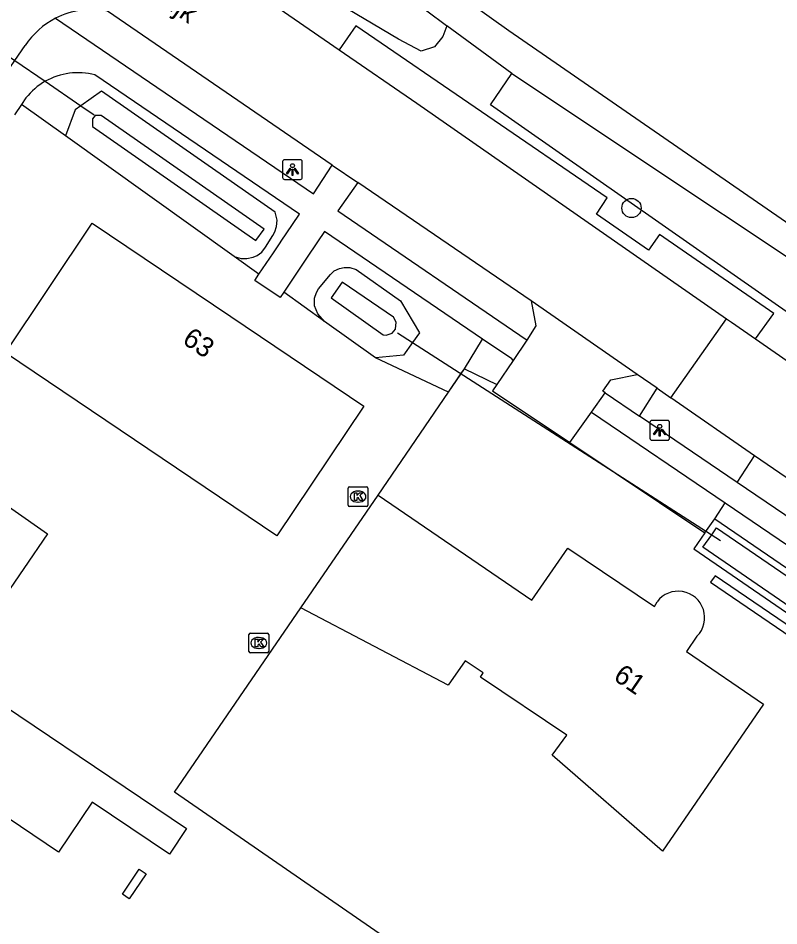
# Model space of a CAD drawing. Extents: x 163863 to 164644, y 379566 to 382155.
# Drawn here: x 164198.04 to 164236.59, y 381807.43 to 381853.41 of the extents above; entities that cross this region are included whole.
import ezdxf

# ---------------------------------------------------------------- set-up
doc = ezdxf.new("R2010")
doc.units = 0
for name, color, linetype in [('IMGEO_Boom', 7, 'Continuous'), ('IMGEO_Duiker', 7, 'Continuous'), ('IMGEO_Erf', 7, 'Continuous'), ('IMGEO_Grasland_overig', 7, 'Continuous'), ('IMGEO_Groenvoorziening', 7, 'Continuous'), ('IMGEO_Haag', 7, 'Continuous'), ('IMGEO_Kolk', 7, 'Continuous'), ('IMGEO_Lichtpunt', 7, 'Continuous'), ('IMGEO_Muur', 7, 'Continuous'), ('IMGEO_Openbare_ruimte_label', 7, 'Continuous'), ('IMGEO_Pand', 7, 'Continuous'), ('IMGEO_Pand_nummerreeks', 7, 'Continuous'), ('IMGEO_Parkeervlak_halfverhard', 7, 'Continuous'), ('IMGEO_Parkeervlak_open', 7, 'Continuous'), ('IMGEO_Rijbaan_lokaal_gesloten', 7, 'Continuous'), ('IMGEO_Rijbaan_lokaal_open', 7, 'Continuous'), ('IMGEO_Sloot', 7, 'Continuous'), ('IMGEO_Voetpad_open', 7, 'Continuous'), ('IMGEO_Waterloop', 7, 'Continuous')]:
    doc.layers.add(name, color=color, linetype=linetype)

msp = doc.modelspace()

# ---------------------------------------------------------------- linework, layer by layer
at = {"layer": 'IMGEO_Boom'}
msp.add_circle((164229.12, 381843.797), 0.489, dxfattribs=at)
at = {"layer": 'IMGEO_Duiker'}
for points in [[(164190.042, 381856.658), (164190.846, 381856.104), (164192.323, 381855.089), (164194.104, 381853.864), (164197.871, 381851.272), (164199.409, 381850.214), (164201.216, 381848.971), (164201.883, 381848.512)], [(164217.268, 381837.469), (164218.022, 381836.985), (164233.632, 381826.955)]]:
    msp.add_lwpolyline(points, dxfattribs=at)
at = {"layer": 'IMGEO_Erf'}
for points in [[(164208.977, 381841.341), (164200.437, 381847.454)], [(164216.141, 381836.213), (164213.566, 381838.056)], [(164216.274, 381829.253), (164219.843, 381834.466)], [(164232.842, 381827.338), (164232.273, 381826.526), (164254.142, 381811.525), (164254.893, 381811.01), (164255.882, 381812.656)], [(164234.237, 381791.715), (164235.601, 381793.483), (164235.285, 381793.932), (164235.043, 381794.138), (164205.955, 381814.209), (164212.364, 381823.54)]]:
    msp.add_lwpolyline(points, dxfattribs=at)
at = {"layer": 'IMGEO_Grasland_overig'}
for points in [[(164335.006, 381775.051), (164322.428, 381783.408), (164286.005, 381809.753), (164256.457, 381829.627), (164222.906, 381852.769), (164211.763, 381860.7), (164201.663, 381868.745), (164208.654, 381876.058), (164252.396, 381909.265)], [(164223.061, 381850.617), (164219.769, 381853.023)], [(164208.977, 381841.341), (164209.344, 381841.247), (164209.632, 381841.24), (164209.943, 381841.299), (164210.157, 381841.388), (164210.386, 381841.558), (164210.564, 381841.812), (164210.941, 381842.409), (164211.052, 381842.593), (164211.125, 381842.859), (164211.155, 381843.184), (164211.061, 381843.586), (164202.265, 381849.716), (164201.216, 381848.971), (164200.931, 381848.768), (164200.437, 381847.454)], [(164200.437, 381847.454), (164198.212, 381849.047)], [(164210.234, 381840.441), (164208.977, 381841.341)]]:
    msp.add_lwpolyline(points, dxfattribs=at)
at = {"layer": 'IMGEO_Groenvoorziening'}
for points in [[(164213.566, 381838.056), (164213.223, 381838.437), (164213.061, 381838.836), (164213.061, 381839.228), (164213.15, 381839.509), (164213.258, 381839.698), (164213.869, 381840.436), (164214.044, 381840.618), (164214.325, 381840.736), (164214.561, 381840.788), (164214.849, 381840.78), (164215.169, 381840.688), (164217.418, 381839.098), (164218.372, 381837.475), (164218.022, 381836.985), (164217.566, 381836.344), (164216.141, 381836.213)], [(164213.566, 381838.056), (164211.492, 381839.541)], [(164220.66, 381835.65), (164221.574, 381837.159)], [(164219.843, 381834.466), (164216.141, 381836.213)], [(164219.843, 381834.466), (164220.66, 381835.65)], [(164220.66, 381835.65), (164222.298, 381834.862)], [(164233.34, 381828.049), (164255.882, 381812.656)]]:
    msp.add_lwpolyline(points, dxfattribs=at)
at = {"layer": 'IMGEO_Haag'}
msp.add_lwpolyline([(164233.352, 381825.171), (164233.126, 381824.841), (164253.669, 381810.851), (164253.894, 381811.182), (164233.352, 381825.171)], dxfattribs=at)
at = {"layer": 'IMGEO_Kolk'}
for p, q in [((164214.759, 381828.751), (164214.759, 381829.603)), ((164214.834, 381829.677), (164215.686, 381829.677)), ((164215.247, 381829.457), (164215.272, 381829.457)), ((164215.76, 381829.603), (164215.76, 381828.751)), ((164215.686, 381828.677), (164214.834, 381828.677)), ((164215.27, 381828.897), (164215.245, 381828.897)), ((164209.734, 381821.337), (164209.734, 381822.189)), ((164209.809, 381822.263), (164210.661, 381822.263)), ((164210.735, 381822.189), (164210.735, 381821.337)), ((164210.222, 381822.043), (164210.247, 381822.043)), ((164210.661, 381821.263), (164209.809, 381821.263)), ((164210.245, 381821.483), (164210.22, 381821.483))]:
    msp.add_line(p, q, dxfattribs=at)
for points in [[(164214.759, 381828.751), (164214.759, 381829.603)], [(164214.834, 381829.677), (164215.686, 381829.677)], [(164215.76, 381829.603), (164215.76, 381828.751)], [(164215.08, 381829.377), (164215.203, 381829.377), (164215.203, 381829.226), (164215.333, 381829.377), (164215.497, 381829.377), (164215.351, 381829.226), (164215.504, 381828.977), (164215.352, 381828.977), (164215.267, 381829.141), (164215.203, 381829.074), (164215.203, 381828.977), (164215.08, 381828.977), (164215.08, 381829.377)], [(164215.686, 381828.677), (164214.834, 381828.677)], [(164209.734, 381821.337), (164209.734, 381822.189)], [(164209.809, 381822.263), (164210.661, 381822.263)], [(164210.735, 381822.189), (164210.735, 381821.337)], [(164210.055, 381821.963), (164210.178, 381821.963), (164210.178, 381821.812), (164210.308, 381821.963), (164210.472, 381821.963), (164210.326, 381821.812), (164210.479, 381821.563), (164210.327, 381821.563), (164210.242, 381821.727), (164210.178, 381821.66), (164210.178, 381821.563), (164210.055, 381821.563), (164210.055, 381821.963)], [(164210.661, 381821.263), (164209.809, 381821.263)]]:
    msp.add_lwpolyline(points, dxfattribs=at)
for centre, start, end in [((164214.836, 381829.601), 91.552, 178.448), ((164214.836, 381829.601), 91.552, 178.448), ((164215.684, 381829.601), 1.552, 88.448), ((164215.684, 381829.601), 1.552, 88.448), ((164214.836, 381828.753), 181.552, 268.448), ((164214.836, 381828.753), 181.552, 268.448), ((164215.684, 381828.753), 271.552, 358.448), ((164215.684, 381828.753), 271.552, 358.448), ((164209.811, 381822.187), 91.552, 178.448), ((164209.811, 381822.187), 91.552, 178.448), ((164210.659, 381822.187), 1.552, 88.448), ((164210.659, 381822.187), 1.552, 88.448), ((164209.811, 381821.339), 181.552, 268.448), ((164209.811, 381821.339), 181.552, 268.448), ((164210.659, 381821.339), 271.552, 358.448), ((164210.659, 381821.339), 271.552, 358.448)]:
    msp.add_arc(centre, 0.0765, start, end, dxfattribs=at)
for centre, major_axis, ratio, start_param, end_param in [((164215.246, 381829.177), (-0.387, 0.002), 0.722429, 4.712389, 7.853982), ((164215.271, 381829.177), (-0.39, 0.002), 0.717154, 1.570796, 4.712389), ((164210.221, 381821.763), (-0.387, 0.002), 0.722429, 4.712389, 7.853982), ((164210.246, 381821.763), (-0.39, 0.002), 0.717154, 1.570796, 4.712389)]:
    msp.add_ellipse(centre, major_axis=major_axis, ratio=ratio, start_param=start_param, end_param=end_param, dxfattribs=at)
at = {"layer": 'IMGEO_Lichtpunt'}
for p, q in [((164211.44, 381846.145), (164211.44, 381845.338)), ((164211.44, 381846.145), (164211.44, 381845.338)), ((164212.342, 381846.24), (164211.534, 381846.24)), ((164212.342, 381846.24), (164211.534, 381846.24)), ((164212.436, 381845.338), (164212.436, 381846.145)), ((164212.436, 381845.338), (164212.436, 381846.145)), ((164211.534, 381845.244), (164212.342, 381845.244)), ((164211.534, 381845.244), (164212.342, 381845.244)), ((164230.051, 381832.938), (164230.051, 381832.131)), ((164230.051, 381832.938), (164230.051, 381832.131)), ((164230.953, 381833.033), (164230.145, 381833.033)), ((164230.953, 381833.033), (164230.145, 381833.033)), ((164231.047, 381832.131), (164231.047, 381832.938)), ((164231.047, 381832.131), (164231.047, 381832.938)), ((164230.145, 381832.037), (164230.953, 381832.037)), ((164230.145, 381832.037), (164230.953, 381832.037))]:
    msp.add_line(p, q, dxfattribs=at)
for points in [[(164211.814, 381845.809), (164211.853, 381845.781), (164211.665, 381845.519), (164211.627, 381845.546), (164211.814, 381845.809)], [(164211.916, 381845.761), (164211.963, 381845.761), (164211.963, 381845.439), (164211.916, 381845.439), (164211.916, 381845.761)], [(164212.026, 381845.781), (164212.064, 381845.808), (164212.251, 381845.546), (164212.212, 381845.518), (164212.026, 381845.781)], [(164230.425, 381832.602), (164230.464, 381832.574), (164230.276, 381832.312), (164230.238, 381832.339), (164230.425, 381832.602)], [(164230.527, 381832.554), (164230.574, 381832.554), (164230.574, 381832.232), (164230.527, 381832.232), (164230.527, 381832.554)], [(164230.637, 381832.574), (164230.675, 381832.601), (164230.862, 381832.339), (164230.823, 381832.311), (164230.637, 381832.574)]]:
    msp.add_lwpolyline(points, dxfattribs=at)
for centre in [(164211.939, 381845.943), (164230.55, 381832.736)]:
    msp.add_circle(centre, 0.0994, dxfattribs=at)
for centre, start, end in [((164211.534, 381846.145), 90, 180), ((164211.534, 381846.145), 90, 180), ((164212.342, 381846.145), 0, 90), ((164212.342, 381846.145), 0, 90), ((164211.534, 381845.338), 180, 270), ((164211.534, 381845.338), 180, 270), ((164212.342, 381845.338), 270, 0), ((164212.342, 381845.338), 270, 360), ((164230.145, 381832.938), 90, 180), ((164230.145, 381832.938), 90, 180), ((164230.953, 381832.938), 0, 90), ((164230.953, 381832.938), 0, 90), ((164230.145, 381832.131), 180, 270), ((164230.145, 381832.131), 180, 270), ((164230.953, 381832.131), 270, 0), ((164230.953, 381832.131), 270, 360)]:
    msp.add_arc(centre, 0.0946, start, end, dxfattribs=at)
at = {"layer": 'IMGEO_Muur'}
for points in [[(164220.477, 381835.391), (164220.655, 381835.651)], [(164219.843, 381834.466), (164220.477, 381835.391)], [(164216.274, 381829.253), (164219.843, 381834.466)], [(164235.043, 381794.138), (164205.955, 381814.209), (164212.364, 381823.54)]]:
    msp.add_lwpolyline(points, dxfattribs=at)
at = {"layer": 'IMGEO_Pand'}
for points in [[(164197.39, 381836.467), (164201.794, 381843.035), (164208.819, 381838.297), (164215.56, 381833.752), (164211.149, 381827.193), (164197.39, 381836.467)], [(164190.351, 381825.963), (164193.911, 381831.206), (164199.528, 381827.3), (164195.916, 381822.029), (164190.351, 381825.963)], [(164212.364, 381823.54), (164216.274, 381829.253)], [(164216.274, 381829.253), (164224.066, 381823.939), (164225.891, 381826.571), (164230.279, 381823.603), (164230.417, 381823.852)], [(164232.439, 381822.106), (164231.909, 381821.33), (164235.808, 381818.657), (164230.696, 381811.217), (164225.107, 381816.082), (164225.837, 381817.086), (164221.471, 381820.037), (164221.61, 381820.246), (164220.683, 381820.865), (164219.83, 381819.623), (164212.364, 381823.54)], [(164179.403, 381809.776), (164187.804, 381822.239), (164192.882, 381818.816), (164194.165, 381820.708), (164206.574, 381812.36), (164205.701, 381811.062), (164201.779, 381813.699), (164200.08, 381811.174), (164193.606, 381815.529), (164186.515, 381804.988), (164179.403, 381809.776)], [(164204.176, 381810.303), (164204.52, 381810.071), (164203.666, 381808.802), (164203.322, 381809.033), (164204.176, 381810.303)]]:
    msp.add_lwpolyline(points, dxfattribs=at)
msp.add_arc((164231.487, 381823.048), 1.339, 315.3117, 143.067, dxfattribs=at)
at = {"layer": 'IMGEO_Parkeervlak_halfverhard'}
msp.add_lwpolyline([(164235.41, 381837.168), (164236.331, 381838.448), (164230.539, 381842.463), (164229.978, 381841.659), (164227.341, 381843.488), (164227.892, 381844.304), (164215.15, 381853.032), (164214.31, 381851.815)], dxfattribs=at)
at = {"layer": 'IMGEO_Parkeervlak_open'}
for points in [[(164229.527, 381833.256), (164230.42, 381834.663)], [(164234.476, 381829.885), (164235.361, 381831.249)]]:
    msp.add_lwpolyline(points, dxfattribs=at)
at = {"layer": 'IMGEO_Rijbaan_lokaal_gesloten'}
for points in [[(164205.181, 381858.114), (164214.31, 381851.815)], [(164213.948, 381845.959), (164202.562, 381853.773)], [(164214.31, 381851.815), (164218.242, 381849.102), (164233.939, 381838.189)], [(164213.948, 381845.959), (164215.248, 381845.088)], [(164224.041, 381839.088), (164215.248, 381845.088)], [(164229.404, 381835.36), (164224.041, 381839.088)], [(164231.119, 381834.18), (164233.939, 381838.189)], [(164233.939, 381838.189), (164234.184, 381838.019), (164235.41, 381837.168)], [(164235.41, 381837.168), (164242.387, 381832.326), (164242.758, 381832.059)], [(164230.42, 381834.663), (164229.404, 381835.36)], [(164230.42, 381834.663), (164231.119, 381834.18)], [(164235.361, 381831.249), (164231.119, 381834.18)], [(164239.966, 381828.066), (164238.288, 381829.227), (164235.361, 381831.249)]]:
    msp.add_lwpolyline(points, dxfattribs=at)
at = {"layer": 'IMGEO_Rijbaan_lokaal_open'}
for points in [[(164196.592, 381849.406), (164197.871, 381851.272), (164198.396, 381852.037)], [(164224.041, 381839.088), (164224.271, 381837.825), (164223.813, 381837.103)], [(164223.813, 381837.103), (164223.128, 381836.076)], [(164223.128, 381836.076), (164222.298, 381834.862)], [(164227.793, 381834.436), (164227.67, 381834.52), (164228.079, 381835.092), (164229.404, 381835.36)], [(164222.298, 381834.862), (164222.08, 381834.543), (164225.998, 381831.919)], [(164227.089, 381833.448), (164227.793, 381834.436)], [(164225.998, 381831.919), (164227.089, 381833.448)]]:
    msp.add_lwpolyline(points, dxfattribs=at)
for centre, radius, start, end in [((164201.76, 381849.906), 3.949, 78.2887, 117.5624), ((164201.849, 381849.71), 4.164, 117.3979, 146.0263)]:
    msp.add_arc(centre, radius, start, end, dxfattribs=at)
at = {"layer": 'IMGEO_Sloot'}
for points in [[(164210.075, 381842.154), (164210.501, 381842.717), (164202.241, 381848.491), (164201.946, 381848.491), (164201.798, 381848.313), (164201.798, 381847.929), (164210.075, 381842.154)], [(164214.453, 381840.037), (164213.901, 381839.242), (164216.535, 381837.376), (164216.683, 381837.362), (164216.993, 381837.465), (164217.156, 381837.657), (164217.2, 381838.012), (164217.052, 381838.263), (164214.453, 381840.037)]]:
    msp.add_lwpolyline(points, dxfattribs=at)
at = {"layer": 'IMGEO_Voetpad_open'}
for points in [[(164199.933, 381853.407), (164213.001, 381844.519), (164213.948, 381845.959)], [(164210.234, 381840.441), (164210.971, 381841.528), (164211.31, 381842.028), (164211.367, 381842.112), (164211.947, 381842.968), (164212.298, 381843.486), (164201.922, 381850.538)], [(164198.432, 381849.375), (164198.212, 381849.047)], [(164198.212, 381849.047), (164197.859, 381848.521)], [(164215.248, 381845.088), (164214.237, 381843.648), (164223.774, 381837.13), (164223.813, 381837.103)], [(164221.574, 381837.159), (164213.561, 381842.608), (164213.204, 381842.078), (164212.655, 381841.264), (164212.135, 381840.494), (164211.492, 381839.541)], [(164211.492, 381839.541), (164211.311, 381839.272), (164210.023, 381840.13), (164210.234, 381840.441)], [(164223.128, 381836.076), (164223.059, 381836.149), (164221.574, 381837.159)], [(164227.793, 381834.436), (164229.527, 381833.256)], [(164227.089, 381833.448), (164233.864, 381828.855)], [(164234.476, 381829.885), (164229.527, 381833.256)], [(164225.998, 381831.919), (164232.842, 381827.338)], [(164257.217, 381814.474), (164234.476, 381829.885)], [(164233.34, 381828.049), (164233.864, 381828.855)], [(164233.864, 381828.855), (164256.552, 381813.463)], [(164232.842, 381827.338), (164233.34, 381828.049)]]:
    msp.add_lwpolyline(points, dxfattribs=at)
for centre, radius, start, end in [((164201.063, 381847.292), 3.358, 75.1807, 119.5125), ((164201.064, 381847.299), 3.352, 119.5802, 141.7285)]:
    msp.add_arc(centre, radius, start, end, dxfattribs=at)
at = {"layer": 'IMGEO_Waterloop'}
for points in [[(164255.409, 381913.055), (164247.863, 381907.224), (164235.639, 381897.964), (164222.992, 381888.227), (164210.557, 381878.702), (164203.175, 381872.987), (164199.682, 381869.415), (164198.747, 381868.31), (164200.241, 381867.209), (164203.607, 381864.729), (164212.773, 381858.254), (164219.743, 381853.042), (164219.769, 381853.023)], [(164219.769, 381853.023), (164219.553, 381852.482), (164219.129, 381851.953), (164218.468, 381851.741), (164217.304, 381852.35), (164212.541, 381855.181), (164205.239, 381860.42), (164197.592, 381866.161), (164196.931, 381866.161), (164195.529, 381866.611), (164195.052, 381867.457), (164195.268, 381868.391), (164195.29, 381868.489), (164195.394, 381868.583)], [(164362.019, 381753.203), (164361.428, 381751.86), (164361.269, 381751.975), (164350.837, 381759.485), (164291.421, 381800.511), (164261.825, 381821.183), (164221.968, 381849.023), (164223.061, 381850.617)], [(164223.061, 381850.617), (164244.45, 381836.352), (164263.512, 381823.639), (164264.597, 381822.915), (164293.413, 381802.563), (164333.203, 381774.002)], [(164233.424, 381827.588), (164255.434, 381812.558), (164254.79, 381811.485), (164254.331, 381811.8), (164232.739, 381826.61), (164233.183, 381827.244), (164233.424, 381827.588)]]:
    msp.add_lwpolyline(points, dxfattribs=at)

# ---------------------------------------------------------------- texts
at = {"layer": 'IMGEO_Openbare_ruimte_label'}
msp.add_text('Rielsedijk', height=1, rotation=324.6089, dxfattribs=at).set_placement((164202.012, 381856.426))
at = {"layer": 'IMGEO_Pand_nummerreeks'}
for s, rotation, p in [('63', 325.995, (164206.3, 381836.981)), ('61', 325.567, (164228.147, 381819.932))]:
    msp.add_text(s, height=1, rotation=rotation, dxfattribs=at).set_placement(p)

doc.saveas('drawing.dxf')
